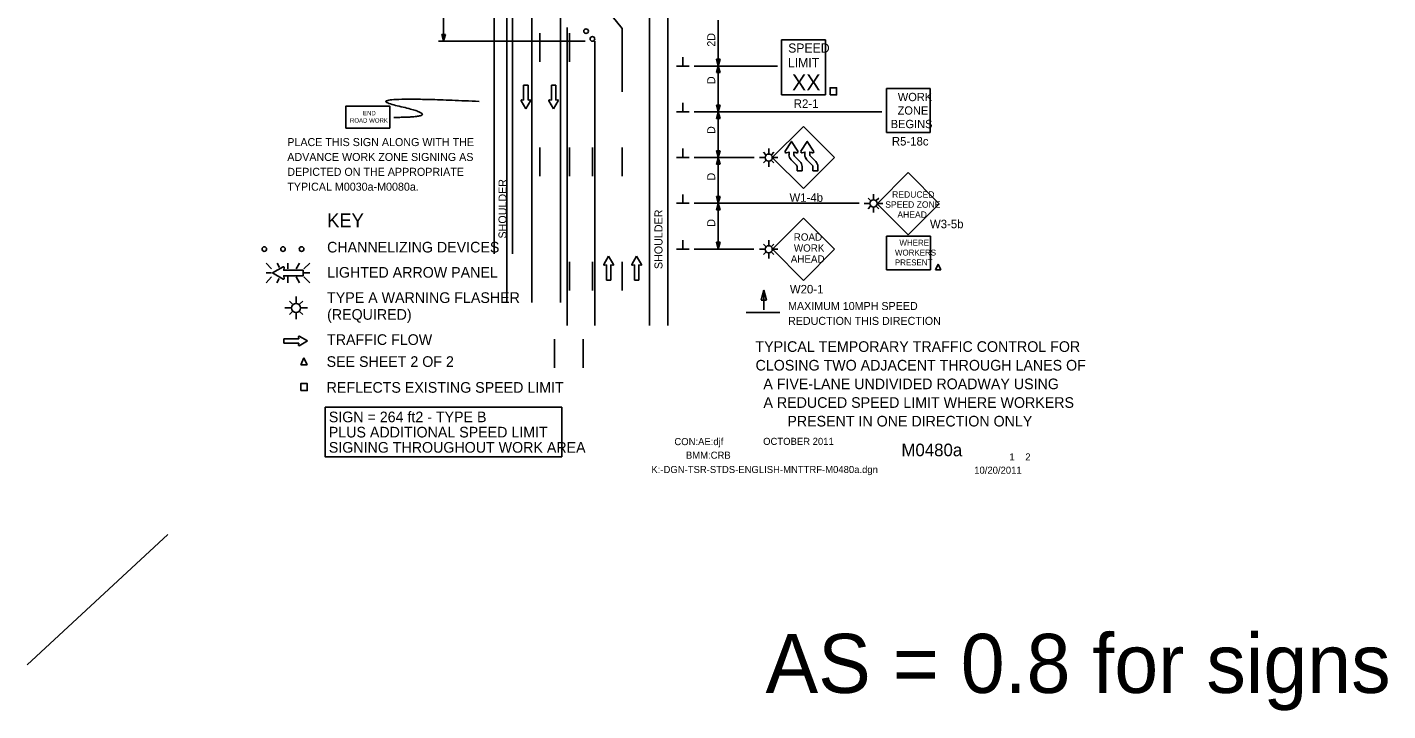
# Model space of a CAD drawing. Extents: x 16525 to 18479, y 5726 to 6926.
# Drawn here: x 16525 to 17715, y 5726 to 6323 of the extents above; entities that cross this region are included whole.
import ezdxf

# ---------------------------------------------------------------- set-up
doc = ezdxf.new("R2010")
doc.units = 0
for name, color, linetype in [('ALI_LEGAL_EX', 7, 'Continuous'), ('BORDER', 7, 'Continuous'), ('BORDER_SIGNAL_WO', 7, 'Continuous'), ('MT_SCRATCH_LEVEL_E', 7, 'Continuous'), ('PAVT_EDGE_EX', 7, 'Continuous'), ('TRAFFIC_SIGNS_PR', 7, 'Continuous'), ('TYPICAL_TEXT_DIMEN_EX', 7, 'Continuous'), ('TYPICAL_TEXT_DIMEN_PR', 7, 'Continuous')]:
    doc.layers.add(name, color=color, linetype=linetype)

msp = doc.modelspace()

# ---------------------------------------------------------------- linework, layer by layer
at = {"layer": 'ALI_LEGAL_EX'}
for points in [[(16973, 6318.2), (16973, 6293.2)], [(16999, 6318.2), (16999, 6293.2)], [(16973, 6218.2), (16973, 6193.2)], [(16999, 6218.2), (16999, 6193.2)], [(17019, 6218.2), (17019, 6193.2)], [(17045, 6218.2), (17045, 6193.2)], [(16999, 6118.2), (16999, 6093.2)], [(17019, 6118.2), (17019, 6093.2)], [(17045, 6118.2), (17045, 6093.2)]]:
    msp.add_lwpolyline(points, dxfattribs=at)
at = {"layer": 'MT_SCRATCH_LEVEL_E'}
for p, q in [((16962.7, 6272.8), (16958.9, 6272.8)), ((16958.9, 6272.8), (16958.9, 6259.6)), ((16962.7, 6272.8), (16958.9, 6272.8)), ((16958.9, 6272.8), (16958.9, 6259.6)), ((16962.7, 6259.6), (16962.7, 6272.8)), ((16962.7, 6259.6), (16962.7, 6272.8)), ((16986.9, 6272.8), (16983.2, 6272.8)), ((16983.2, 6272.8), (16983.2, 6259.6)), ((16986.9, 6272.8), (16983.2, 6272.8)), ((16983.2, 6272.8), (16983.2, 6259.6)), ((16986.9, 6259.6), (16986.9, 6272.8)), ((16986.9, 6259.6), (16986.9, 6272.8)), ((16956.7, 6259.2), (16960.8, 6252)), ((16956.7, 6259.2), (16960.8, 6252)), ((16958.9, 6259.6), (16957.1, 6259.9)), ((16958.9, 6259.6), (16957.1, 6259.9)), ((16960.8, 6252), (16964.9, 6259.2)), ((16960.8, 6252), (16964.9, 6259.2)), ((16964.4, 6259.9), (16962.7, 6259.6)), ((16964.4, 6259.9), (16962.7, 6259.6)), ((16980.9, 6259.2), (16985.1, 6252)), ((16980.9, 6259.2), (16985.1, 6252)), ((16983.2, 6259.6), (16981.4, 6259.9)), ((16983.2, 6259.6), (16981.4, 6259.9)), ((16985.1, 6252), (16989.2, 6259.2)), ((16985.1, 6252), (16989.2, 6259.2)), ((16988.7, 6259.9), (16986.9, 6259.6)), ((16988.7, 6259.9), (16986.9, 6259.6)), ((17033.2, 6123.2), (17029.1, 6115.9)), ((17033.2, 6123.2), (17029.1, 6115.9)), ((17037.4, 6115.9), (17033.2, 6123.2)), ((17037.4, 6115.9), (17033.2, 6123.2)), ((17057.7, 6123.2), (17053.6, 6115.9)), ((17057.7, 6123.2), (17053.6, 6115.9)), ((17061.9, 6115.9), (17057.7, 6123.2)), ((17061.9, 6115.9), (17057.7, 6123.2)), ((17029.6, 6115.3), (17031.4, 6115.6)), ((17029.6, 6115.3), (17031.4, 6115.6)), ((17031.4, 6115.6), (17031.4, 6102.3)), ((17031.4, 6115.6), (17031.4, 6102.3)), ((17035.1, 6102.3), (17035.1, 6115.6)), ((17035.1, 6115.6), (17036.9, 6115.3)), ((17035.1, 6102.3), (17035.1, 6115.6)), ((17035.1, 6115.6), (17036.9, 6115.3)), ((17054.1, 6115.3), (17055.9, 6115.6)), ((17054.1, 6115.3), (17055.9, 6115.6)), ((17055.9, 6115.6), (17055.9, 6102.3)), ((17055.9, 6115.6), (17055.9, 6102.3)), ((17059.6, 6102.3), (17059.6, 6115.6)), ((17059.6, 6115.6), (17061.4, 6115.3)), ((17059.6, 6102.3), (17059.6, 6115.6)), ((17059.6, 6115.6), (17061.4, 6115.3)), ((17031.4, 6102.3), (17035.1, 6102.3)), ((17031.4, 6102.3), (17035.1, 6102.3)), ((17055.9, 6102.3), (17059.6, 6102.3)), ((17055.9, 6102.3), (17059.6, 6102.3)), ((16762.3, 6051), (16749.1, 6051)), ((16749.1, 6051), (16749.1, 6047.3)), ((16762.3, 6051), (16749.1, 6051)), ((16749.1, 6051), (16749.1, 6047.3)), ((16749.1, 6047.3), (16762.3, 6047.3)), ((16749.1, 6047.3), (16762.3, 6047.3)), ((16762, 6052.8), (16762.3, 6051)), ((16762, 6052.8), (16762.3, 6051)), ((16762.3, 6047.3), (16762, 6045.5)), ((16762.3, 6047.3), (16762, 6045.5)), ((16769.9, 6049.2), (16762.7, 6053.3)), ((16769.9, 6049.2), (16762.7, 6053.3)), ((16762.7, 6045), (16769.9, 6049.2)), ((16762.7, 6045), (16769.9, 6049.2))]:
    msp.add_line(p, q, dxfattribs=at)
for centre, start, end in [((16957.1, 6259.4), 80.0362, 209.7731), ((16957.1, 6259.4), 80.0362, 209.7731), ((16964.5, 6259.4), 330.4248, 99.9638), ((16964.5, 6259.4), 330.4248, 99.9638), ((16981.3, 6259.4), 80.0362, 209.7731), ((16981.3, 6259.4), 80.0362, 209.7731), ((16988.8, 6259.4), 330.4248, 99.9638), ((16988.8, 6259.4), 330.4248, 99.9638), ((17029.5, 6115.7), 150.4248, 279.9638), ((17029.5, 6115.7), 150.4248, 279.9638), ((17037, 6115.7), 260.0362, 29.7731), ((17037, 6115.7), 260.0362, 29.7731), ((17054, 6115.7), 150.4248, 279.9638), ((17054, 6115.7), 150.4248, 279.9638), ((17061.5, 6115.7), 260.0362, 29.7731), ((17061.5, 6115.7), 260.0362, 29.7731), ((16762.5, 6052.9), 60.4248, 189.9638), ((16762.5, 6052.9), 60.4248, 189.9638), ((16762.5, 6045.5), 170.0362, 299.7731), ((16762.5, 6045.5), 170.0362, 299.7731)]:
    msp.add_arc(centre, 0.463, start, end, dxfattribs=at)
at = {"layer": 'PAVT_EDGE_EX'}
for p, q in [((16933, 6926.1), (16933, 6125.4)), ((16949, 6926.1), (16949, 6125.4)), ((17069, 6926.1), (17069, 6062.8)), ((17085, 6926.1), (17085, 6062.8)), ((16944.1, 6912.1), (16944.1, 6082.9)), ((16966.1, 6912.1), (16966.1, 6082.9)), ((16991.1, 6912.1), (16991.1, 6082.9)), ((16997, 6382), (17045, 6322.3)), ((16997, 6323.2), (16997, 6062.8)), ((17045, 6322.3), (17045, 6266.9)), ((17021, 6311.2), (17021, 6062.8))]:
    msp.add_line(p, q, dxfattribs=at)
for points in [[(16985.8, 6025.7), (16985.8, 6050.7)], [(16985.8, 6025.7), (16985.8, 6050.7)], [(17010.8, 6025.7), (17010.8, 6050.7)], [(17010.8, 6025.7), (17010.8, 6050.7)]]:
    msp.add_lwpolyline(points, dxfattribs=at)
at = {"layer": 'TRAFFIC_SIGNS_PR'}
for p, q in [((17184.4, 6312.3), (17222.8, 6312.3)), ((17184.4, 6264.3), (17184.4, 6312.3)), ((17222.8, 6264.3), (17222.8, 6312.3)), ((17184.4, 6264.3), (17222.8, 6264.3)), ((17276.1, 6231.4), (17276.1, 6269.8)), ((17276.1, 6269.8), (17314.5, 6269.8)), ((17314.5, 6231.4), (17314.5, 6269.8)), ((17176.3, 6209.4), (17203.5, 6236.6)), ((17203.5, 6236.6), (17230.6, 6209.4)), ((17276.1, 6231.4), (17314.5, 6231.4)), ((17170.7, 6212), (17168.6, 6214.1)), ((17173.2, 6213), (17173.2, 6217.5)), ((17175.7, 6212), (17177.8, 6214.1)), ((17170, 6209.4), (17165.2, 6209.4)), ((17170.7, 6206.9), (17168.6, 6204.8)), ((17173.2, 6201.5), (17173.2, 6205.9)), ((17175.7, 6206.9), (17177.8, 6204.8)), ((17176.3, 6209.4), (17181.2, 6209.4)), ((17203.5, 6182.3), (17176.3, 6209.4)), ((17197.5, 6202.9), (17192.8, 6207.6)), ((17197.5, 6202.9), (17192.8, 6207.6)), ((17200.5, 6206), (17195.8, 6210.7)), ((17195.8, 6210.7), (17200.5, 6206)), ((17198.1, 6197.9), (17198.1, 6201.6)), ((17202.4, 6197.9), (17202.4, 6201.6)), ((17230.6, 6209.4), (17203.5, 6182.3)), ((17211.3, 6202.9), (17206.6, 6207.6)), ((17211.3, 6202.9), (17206.6, 6207.6)), ((17214.3, 6206), (17209.6, 6210.7)), ((17209.6, 6210.7), (17214.3, 6206)), ((17211.9, 6197.9), (17211.9, 6201.6)), ((17216.2, 6197.9), (17216.2, 6201.6)), ((17202.4, 6197.9), (17198.1, 6197.9)), ((17216.2, 6197.9), (17211.9, 6197.9)), ((17295.1, 6196.3), (17267.9, 6169.1)), ((17322.2, 6169.1), (17295.1, 6196.3)), ((17264.8, 6173), (17264.8, 6177.5)), ((17261.7, 6169.4), (17256.8, 6169.4)), ((17262.3, 6171.9), (17260.2, 6174)), ((17262.3, 6166.9), (17260.2, 6164.8)), ((17264.8, 6161.4), (17264.8, 6165.9)), ((17267.3, 6171.9), (17269.4, 6174)), ((17267.3, 6166.9), (17269.4, 6164.8)), ((17267.9, 6169.1), (17295.1, 6142)), ((17268, 6169.4), (17272.9, 6169.4)), ((17295.1, 6142), (17322.2, 6169.1)), ((17203.5, 6156.5), (17176.4, 6129.3)), ((17230.7, 6129.3), (17203.5, 6156.5)), ((17276.2, 6140.7), (17314.6, 6140.7)), ((17276.2, 6111.4), (17276.2, 6140.7)), ((17314.6, 6111.4), (17314.6, 6140.7)), ((17170, 6129.3), (17165.2, 6129.3)), ((17170.7, 6131.8), (17168.6, 6133.9)), ((17173.2, 6132.9), (17173.2, 6137.4)), ((17175.7, 6131.8), (17177.8, 6133.9)), ((17176.4, 6129.3), (17181.2, 6129.3)), ((17176.4, 6129.3), (17203.5, 6102.1)), ((17203.5, 6102.1), (17230.7, 6129.3)), ((16733.6, 6117.1), (16738.5, 6112.2)), ((16745.4, 6113.3), (16743.2, 6117.1)), ((16752.7, 6112.2), (16752.7, 6117.1)), ((16759.9, 6112.2), (16762.8, 6117.1)), ((16766.8, 6112.2), (16771.8, 6117.1)), ((17170.7, 6126.8), (17168.6, 6124.7)), ((17173.2, 6121.3), (17173.2, 6125.7)), ((17175.7, 6126.8), (17177.8, 6124.7)), ((16738.5, 6108.6), (16733.6, 6108.6)), ((16733.6, 6100.1), (16738.5, 6105.1)), ((16743.1, 6100.1), (16745.2, 6103.8)), ((16752.7, 6105.1), (16752.7, 6100.1)), ((16762.8, 6100.1), (16760, 6105.1)), ((16766.8, 6108.6), (16771.8, 6108.6)), ((16766.8, 6105.1), (16771.8, 6100.1)), ((17276.2, 6111.4), (17314.6, 6111.4)), ((16756.8, 6081.2), (16754.1, 6083.8)), ((16756.8, 6081.2), (16754.1, 6083.8)), ((16759.9, 6082.5), (16759.9, 6088.1)), ((16759.9, 6082.5), (16759.9, 6088.1)), ((16763, 6081.2), (16765.7, 6083.8)), ((16763, 6081.2), (16765.7, 6083.8)), ((16756, 6078), (16749.9, 6078)), ((16756, 6078), (16749.9, 6078)), ((16756.8, 6074.9), (16754.1, 6072.3)), ((16756.8, 6074.9), (16754.1, 6072.3)), ((16759.9, 6068.1), (16759.9, 6073.6)), ((16759.9, 6068.1), (16759.9, 6073.6)), ((16763, 6074.9), (16765.7, 6072.3)), ((16763, 6074.9), (16765.7, 6072.3)), ((16763.8, 6078), (16769.9, 6078)), ((16763.8, 6078), (16769.9, 6078))]:
    msp.add_line(p, q, dxfattribs=at)
for points in [[(17226.9, 6264.3), (17232.5, 6264.3), (17232.5, 6270.5), (17226.9, 6270.5)], [(16803.4, 6235.3), (16841.8, 6235.3), (16841.8, 6254.5), (16803.4, 6254.5)], [(16764, 6005.8), (16769.6, 6005.8), (16769.6, 6011.9), (16764, 6011.9)]]:
    msp.add_lwpolyline(points, close=True, dxfattribs=at)
for points in [[(17187.6, 6215), (17193.1, 6223.6), (17198.6, 6215)], [(17187.6, 6215), (17193.1, 6223.6), (17198.6, 6215)], [(17201.4, 6215), (17206.9, 6223.6), (17212.4, 6215)], [(17201.4, 6215), (17206.9, 6223.6), (17212.4, 6215)], [(17191, 6211.9), (17191, 6214.3), (17188.6, 6213.7)], [(17191, 6211.9), (17191, 6214.3), (17188.6, 6213.7)], [(17197.6, 6213.7), (17195.3, 6214.3), (17195.3, 6212)], [(17197.6, 6213.7), (17196.8, 6213.9), (17195.3, 6214.3), (17195.3, 6212)], [(17204.8, 6211.9), (17204.8, 6214.3), (17202.4, 6213.7)], [(17204.8, 6211.9), (17204.8, 6214.3), (17202.4, 6213.7)], [(17211.4, 6213.7), (17209.1, 6214.3), (17209.1, 6212)], [(17211.4, 6213.7), (17210.6, 6213.9), (17209.1, 6214.3), (17209.1, 6212)], [(17202.4, 6201.6), (17202.4, 6197.9), (17198.1, 6197.9), (17198.1, 6201.6)], [(17216.2, 6201.6), (17216.2, 6197.9), (17211.9, 6197.9), (17211.9, 6201.6)], [(17321.3, 6116.3), (17319.1, 6111.4)], [(17319.1, 6111.4), (17321.3, 6116.3)], [(17323.6, 6111.4), (17321.3, 6116.3)], [(17321.3, 6116.3), (17323.6, 6111.4)], [(16748.6, 6113.9), (16739.3, 6108.6), (16748.6, 6103.3)], [(16749.5, 6103.9), (16749.1, 6106.2), (16766.1, 6106.2), (16766.1, 6111), (16749.1, 6111), (16749.5, 6113.3)], [(17319.1, 6111.4), (17323.6, 6111.4)], [(17323.6, 6111.4), (17319.1, 6111.4)], [(16766.8, 6034.5), (16764, 6028.4)], [(16764, 6028.4), (16766.8, 6034.5)], [(16769.6, 6028.4), (16766.8, 6034.5)], [(16766.8, 6034.5), (16769.6, 6028.4)], [(16764, 6028.4), (16769.6, 6028.4)], [(16769.6, 6028.4), (16764, 6028.4)]]:
    msp.add_lwpolyline(points, dxfattribs=at)
for centre, radius in [((17013.5, 6320), 2), ((17019, 6313.2), 2), ((17173.2, 6209.4), 3.15), ((17264.8, 6169.4), 3.15), ((16732.1, 6129.5), 2), ((16748.4, 6129.5), 2), ((16764.7, 6129.5), 2), ((17173.2, 6129.3), 3.15), ((16759.9, 6078), 3.94), ((16759.9, 6078), 3.94)]:
    msp.add_circle(centre, radius, dxfattribs=at)
for centre, radius, start, end in [((17188.4, 6214.5), 0.866, 147.7292, 285.3172), ((17188.4, 6214.5), 0.866, 147.7196, 285.3201), ((17178.5, 6220.8), 10.8, 327.5335, 327.5431), ((17191.4, 6203.2), 10.8, 105.3192, 105.32), ((17197.1, 6212), 6.17, 180.6181, 225.7875), ((17197.1, 6212), 6.17, 180.6245, 225.2313), ((17197.1, 6212), 1.85, 180, 225.7875), ((17197.1, 6212), 1.85, 179.8762, 225.7877), ((17197.9, 6214.5), 0.864, 254.6014, 32.4796), ((17197.9, 6214.5), 0.866, 254.6148, 32.4712), ((17202.2, 6214.5), 0.866, 147.7292, 285.3172), ((17202.2, 6214.5), 0.866, 147.7196, 285.3201), ((17192.3, 6220.8), 10.8, 327.5335, 327.5431), ((17205.2, 6203.2), 10.8, 105.3192, 105.32), ((17210.9, 6212), 6.17, 180.6181, 225.7875), ((17210.9, 6212), 6.17, 180.6245, 225.2313), ((17210.9, 6212), 1.85, 180, 225.7875), ((17210.9, 6212), 1.85, 179.8762, 225.7877), ((17211.7, 6214.5), 0.864, 254.6014, 32.4796), ((17211.7, 6214.5), 0.866, 254.6148, 32.4712), ((17196.2, 6201.6), 1.85, 0, 45.7875), ((17196.2, 6201.6), 1.85, 0, 47.628), ((17196.2, 6201.6), 6.17, 0, 45.7875), ((17196.2, 6201.6), 6.17, 0, 45.7875), ((17196.2, 6201.6), 6.17, 0, 45.7883), ((17210, 6201.6), 1.85, 0, 45.7875), ((17210, 6201.6), 1.85, 0, 47.628), ((17210, 6201.6), 6.17, 0, 45.7875), ((17210, 6201.6), 6.17, 0, 45.7875), ((17210, 6201.6), 6.17, 0, 45.7883), ((16748.9, 6113.4), 0.598, 350.7308, 118.8916), ((16748.9, 6103.8), 0.597, 241.4833, 9.9593)]:
    msp.add_arc(centre, radius, start, end, dxfattribs=at)
msp.add_open_spline([(16845.4, 6244.6), (16892.7, 6244.6), (16807.6, 6264), (16919.9, 6258.5)], degree=2, dxfattribs=at)
at = {"layer": 'TYPICAL_TEXT_DIMEN_EX'}
msp.add_lwpolyline([(16785.2, 5991.2), (16992.2, 5991.2), (16992.2, 5947.9), (16785.2, 5947.9)], close=True, dxfattribs=at)
at = {"layer": 'TYPICAL_TEXT_DIMEN_PR'}
for p, q in [((16888.9, 6311.2), (16888.9, 6369.8)), ((17129, 6329.5), (17129, 6289.5)), ((16884.3, 6311.2), (17012.7, 6311.2)), ((16888.9, 6311.2), (16887.3, 6317)), ((16887.3, 6317), (16888.9, 6317)), ((16888.9, 6317), (16890.5, 6317)), ((16890.5, 6317), (16888.9, 6311.2)), ((17098.1, 6289.5), (17098.1, 6297.3)), ((17129, 6289.5), (17127.4, 6295.4)), ((17127.4, 6295.4), (17129, 6295.4)), ((17129, 6295.4), (17130.6, 6295.4)), ((17130.6, 6295.4), (17129, 6289.5)), ((17103.7, 6289.5), (17092.5, 6289.5)), ((17180.8, 6289.5), (17108, 6289.5)), ((17127.4, 6283.7), (17129, 6289.5)), ((17129, 6283.7), (17127.4, 6283.7)), ((17129, 6289.5), (17130.6, 6283.7)), ((17129, 6289.5), (17129, 6249.5)), ((17130.6, 6283.7), (17129, 6283.7)), ((17103.7, 6249.5), (17092.5, 6249.5)), ((17098.1, 6249.5), (17098.1, 6257.3)), ((17108, 6249.5), (17272, 6249.5)), ((17129, 6249.5), (17127.4, 6255.4)), ((17127.4, 6255.4), (17129, 6255.4)), ((17127.4, 6243.7), (17129, 6249.5)), ((17129, 6255.4), (17130.6, 6255.4)), ((17130.6, 6255.4), (17129, 6249.5)), ((17129, 6249.5), (17130.6, 6243.7)), ((17129, 6249.5), (17129, 6209.5)), ((17129, 6243.7), (17127.4, 6243.7)), ((17130.6, 6243.7), (17129, 6243.7)), ((17098.1, 6209.5), (17098.1, 6217.3)), ((17129, 6209.5), (17127.4, 6215.4)), ((17127.4, 6215.4), (17129, 6215.4)), ((17129, 6215.4), (17130.6, 6215.4)), ((17130.6, 6215.4), (17129, 6209.5)), ((17103.7, 6209.5), (17092.5, 6209.5)), ((17108, 6209.5), (17160.4, 6209.5)), ((17127.4, 6203.7), (17129, 6209.5)), ((17129, 6203.7), (17127.4, 6203.7)), ((17129, 6209.5), (17130.6, 6203.7)), ((17129, 6209.5), (17129, 6169.5)), ((17130.6, 6203.7), (17129, 6203.7)), ((17098.1, 6169.5), (17098.1, 6177.3)), ((17129, 6169.5), (17127.4, 6175.4)), ((17127.4, 6175.4), (17129, 6175.4)), ((17129, 6175.4), (17130.6, 6175.4)), ((17130.6, 6175.4), (17129, 6169.5)), ((17103.7, 6169.5), (17092.5, 6169.5)), ((17252.4, 6169.5), (17108, 6169.5)), ((17127.4, 6163.7), (17129, 6169.5)), ((17129, 6163.7), (17127.4, 6163.7)), ((17129, 6169.5), (17130.6, 6163.7)), ((17129, 6169.5), (17129, 6129.5)), ((17130.6, 6163.7), (17129, 6163.7)), ((17103.7, 6129.5), (17092.5, 6129.5)), ((17098.1, 6129.5), (17098.1, 6137.3)), ((17108, 6129.5), (17160.2, 6129.5)), ((17129, 6129.5), (17127.4, 6135.4)), ((17127.4, 6135.4), (17129, 6135.4)), ((17129, 6135.4), (17130.6, 6135.4)), ((17130.6, 6135.4), (17129, 6129.5)), ((17166.5, 6084.9), (17168.8, 6093.6)), ((17168.8, 6076.5), (17168.8, 6093.6)), ((17168.8, 6093.6), (17171.2, 6084.9)), ((17168.8, 6084.9), (17166.5, 6084.9)), ((17171.2, 6084.9), (17168.8, 6084.9)), ((17183, 6074), (17153.6, 6074)), ((16647.8, 5880), (16524.8, 5766.2))]:
    msp.add_line(p, q, dxfattribs=at)

# ---------------------------------------------------------------- texts
at = {"layer": 'BORDER'}
for s, p in [('TYPICAL TEMPORARY TRAFFIC CONTROL FOR', (17161.6, 6039.6)), ('CLOSING TWO ADJACENT THROUGH LANES OF', (17161.7, 6023.3)), ('A FIVE-LANE UNDIVIDED ROADWAY USING', (17168.5, 6007)), ('A REDUCED SPEED LIMIT WHERE WORKERS', (17168.6, 5990.7)), ('PRESENT IN ONE DIRECTION ONLY', (17189.5, 5974.4))]:
    msp.add_text(s, height=9.3, dxfattribs=at).set_placement(p)
at = {"layer": 'BORDER_SIGNAL_WO'}
for s, height, p in [('CON:AE:djf', 6.2, (17090.7, 5958.1)), ('    OCTOBER 2011    ', 6.2, (17159.1, 5958.3)), ('BMM:CRB   ', 6.2, (17100.8, 5946.2)), ('    M0480a   ', 11, (17272.9, 5948.4)), (' 1    2 ', 6.2, (17381.4, 5944.7)), ('K:-DGN-TSR-STDS-ENGLISH-MNTTRF-M0480a.dgn        ', 6.2, (17070.6, 5933.7)), ('10/20/2011    ', 6.2, (17352.9, 5933.1)), ('AS = 0.8 for signs', 51.61, (17170.4, 5741.5))]:
    msp.add_text(s, height=height, dxfattribs=at).set_placement(p)
at = {"layer": 'TRAFFIC_SIGNS_PR'}
for s, height, p in [('SPEED', 8, (17190.2, 6301.2)), ('LIMIT', 8, (17190, 6288.4)), ('XX', 14.03, (17193.5, 6268.1)), ('R2-1', 7.44, (17195.1, 6252.9)), ('WORK', 7.22, (17286.1, 6258.8)), ('END', 3.83, (16818.4, 6246.4)), ('ZONE', 7.22, (17285.9, 6247)), ('ROAD WORK', 3.83, (16807, 6240)), ('BEGINS', 7.22, (17279.9, 6235.2)), ('PLACE THIS SIGN ALONG WITH THE', 7, (16752.2, 6219.5)), ('R5-18c', 7.44, (17280.9, 6220)), ('ADVANCE WORK ZONE SIGNING AS', 7, (16752.2, 6206.5)), ('DEPICTED ON THE APPROPRIATE', 7, (16752.2, 6193.5)), ('TYPICAL M0030a-M0080a.', 7, (16752.2, 6180.5)), ('W1-4b', 7.44, (17191.4, 6170.8)), ('REDUCED', 5.6, (17281.1, 6174.4)), ('SPEED ZONE', 5.6, (17275.1, 6165.6)), ('AHEAD', 5.6, (17285.7, 6156.8)), ('W3-5b', 7.44, (17314.2, 6147.7)), ('ROAD', 6.41, (17195.1, 6136.8)), ('WORK', 6.41, (17195.2, 6127.2)), ('WORKERS', 5.2, (17283.6, 6123.8)), ('WHERE', 5.2, (17287.5, 6132.4)), ('AHEAD', 6.41, (17192.5, 6117.6)), ('PRESENT', 5.2, (17283.5, 6115.2)), ('W20-1', 7.45, (17191.7, 6090.7))]:
    msp.add_text(s, height=height, dxfattribs=at).set_placement(p)
at = {"layer": 'TYPICAL_TEXT_DIMEN_EX'}
for s, height, p in [('KEY', 12, (16787, 6148.6)), ('CHANNELIZING DEVICES', 9.3, (16787, 6126.5)), ('LIGHTED ARROW PANEL', 9.3, (16787, 6104.5)), ('TYPE A WARNING FLASHER', 9.3, (16787, 6082.4)), ('(REQUIRED)', 9.3, (16787, 6067.7)), ('TRAFFIC FLOW', 9.3, (16787, 6045.7)), ('SEE SHEET 2 OF 2', 9.3, (16786.6, 6026.5)), ('REFLECTS EXISTING SPEED LIMIT', 9.3, (16786.6, 6003.9)), ('SIGN = 264 ft2 - TYPE B', 9.3, (16788.5, 5978.1)), ('PLUS ADDITIONAL SPEED LIMIT', 9.3, (16788.5, 5964.8)), ('SIGNING THROUGHOUT WORK AREA', 9.3, (16788.5, 5951.5))]:
    msp.add_text(s, height=height, dxfattribs=at).set_placement(p)
at = {"layer": 'TYPICAL_TEXT_DIMEN_PR'}
for s, p in [('2D', (17126.4, 6306.4)), ('D', (17126.4, 6273.7)), ('D', (17126.4, 6230.1)), ('SHOULDER', (16943.9, 6138.7)), ('D', (17126.4, 6189.4)), ('SHOULDER', (17080.3, 6112)), ('D', (17126.4, 6149))]:
    msp.add_text(s, height=7, rotation=90, dxfattribs=at).set_placement(p)
for s, p in [('MAXIMUM 10MPH SPEED', (17190.1, 6076.2)), ('REDUCTION THIS DIRECTION', (17190.1, 6063.2))]:
    msp.add_text(s, height=7, dxfattribs=at).set_placement(p)

doc.saveas('drawing.dxf')
